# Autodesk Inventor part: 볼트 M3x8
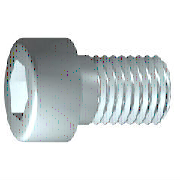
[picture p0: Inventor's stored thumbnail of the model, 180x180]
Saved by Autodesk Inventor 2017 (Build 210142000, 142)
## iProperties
IsCustomPart: 0
Created: 2012-02
Part Number: 볼트 M3x8
Material: 강철, 연강
Description: 6각머리 태핑 나사
Document SubType Name: Modeling
Standard: KS B 1003
Designer: mduedu
Standards Organization: KS
Language: ko-KR
Size Designation: M 3 x 8
Categories: <MemberInstance><Categories><Category DisplayName="조임쇠" InternalName="e4da775c-781d-43d5-af7c-5136215cf5a6" Mnemonic="FSTN"><Category DisplayName="볼트" InternalN
Density: 7.86 g/cm^3
Mass: 0.929843 g
Surface Area: 1.83001 cm^2
Volume: 0.118301 cm^3
Appearance: 강철
Author: mduedu
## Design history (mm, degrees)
sketch "스케치1"
  geometry: L1 (-0.867, 0)-(8, 0); L2 (8, 0)-(8, 1.5); L3 (8, 1.5)-(1.25, 1.5); L4 (1.25, 1.5)-(0.943, 1.5); L5 (0.943, 1.5)-(0, 1.5); L6 (0, 1.5)-(0, 2.75); L7 (0, 2.75)-(-3, 2.75); L8 (-3, 2.75)-(-3, 1.443); L9 (-3, 1.443)-(-1.7, 1.443); L10 (-1.7, 1.443)-(-0.867, 0); L11 (-5.2, 0)-(10.2, 0) reference; L12 (0, -0.55)-(0, 3.3) reference; L13 (1.25, 1.5)-(0, 1.5)
  constraints: 22 end point, 6 parallel, 2 collinear, 2 perpendicular, 1 horizontal, 1 point on line
  dimensions: "d1" = 6.75 distance from line of L3.end L2 (= GEL); "d2" = 0.30683 distance of L4.end L3.end (computed from GAL); "d3" = 3 distance between parallel lines of L8 L6 (= KOH); "d4" = 1.3 distance of L8.end L9.end (= INTI); "d5" = 60 deg angle of L10 L1; "d6" = 3 diameter of L3 L1 (= GD); "d7" = 3 diameter of L5 L1 (= BDM); "d8" = 2.88675 diameter of L9 L1 (= 1.1547 x SW); "d9" = 5.5 diameter of L7 L1 (= KOD); "d26" = 8 distance between parallel lines of L12 L2 (= NLG)
revolve "본체" sketch "스케치1" stored, may be unused: angle "d10" = 90 deg
sketch "스케치2"
  geometry: L1 (0, -3.85)-(0, 3.85) reference; L2 (-3.85, 0)-(3.85, 0) reference; L3 (1.443, 0)-(0.722, -1.25); L4 (0.722, -1.25)-(-0.722, -1.25); L5 (-0.722, -1.25)-(-1.443, 0); L6 (-1.443, 0)-(-0.722, 1.25); L7 (-0.722, 1.25)-(0.722, 1.25); L8 (0.722, 1.25)-(1.443, 0); 2 further points
  constraints: 12 end point, 1 coincident, 1 horizontal alignment, 1 point on line, 12 other
extrude "슬롯" join sketch "스케치2" stored distance "d11" = 10; taper "d12" = 0 deg
workplane "Work Plane1"
fillet "Fillet2" dims "d30" = 0.1 (= R)
body "Solid1"
fillet "모깎기1" dims "d17" = 0.3 (= RR)
feature "스레드" dims "d13" = 6.75 (= GEL), "d14" = 0
chamfer "모따기1" distance "d15" = 0.30673 (= -0.5 x SPD + 0.5 x GD); stored, may be unused: second distance "d16" = 0.30673 (= GUL), angle "d27" = 45 deg
other parameters: "GD" = 3 (= NND) [user parameter; used in 2 equation terms], "NLG" = 8 [user parameter; used in 1 equation term], "GEL" = 6.75 [user parameter; used in 2 equation terms], "KOD" = 5.5 [user parameter; used in 1 equation term], "KOH" = 3 [user parameter; used in 1 equation term], "INTI" = 1.3 [user parameter; used in 1 equation term], "GAL" = 0.30673 (= 0.61345 x PTC) [user parameter; used in 1 equation term], "GUL" = 0.30673 (= 0.61345 x PTC) [user parameter; used in 1 equation term], "BDM" = 3 (= NND) [user parameter; used in 1 equation term], "SW" = 2.5 [user parameter; used in 2 equation terms], "RR" = 0.3 [user parameter; used in 1 equation term], "SPD" = 2.38655 (= NND - 1.2269 x PTC) [user parameter; used in 1 equation term], "d19" = 0, "d28" = 0, "d29" = 0, "R" = 0.1 [user parameter; used in 1 equation term], "PHH" = 0.1 [user parameter], "GD1" = 2.38655 (= THREADDIA - 1.2269 x PTC) [user parameter], "THREADDIA" = 3 [user parameter; used in 1 equation term], "FAWI" = 45 deg [user parameter], "PTC" = 0.5 [user parameter; used in 5 equation terms], "NND" = 3 [user parameter; used in 3 equation terms], "TOA" = 30 deg [user parameter], "E0" = 2.8875 (= 1.155 x SW) [user parameter]
